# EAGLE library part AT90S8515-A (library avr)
MICROCONTROLLER 8 Kbytes FLASH 512 bytes SRAM 512 bytes EEPROM UART
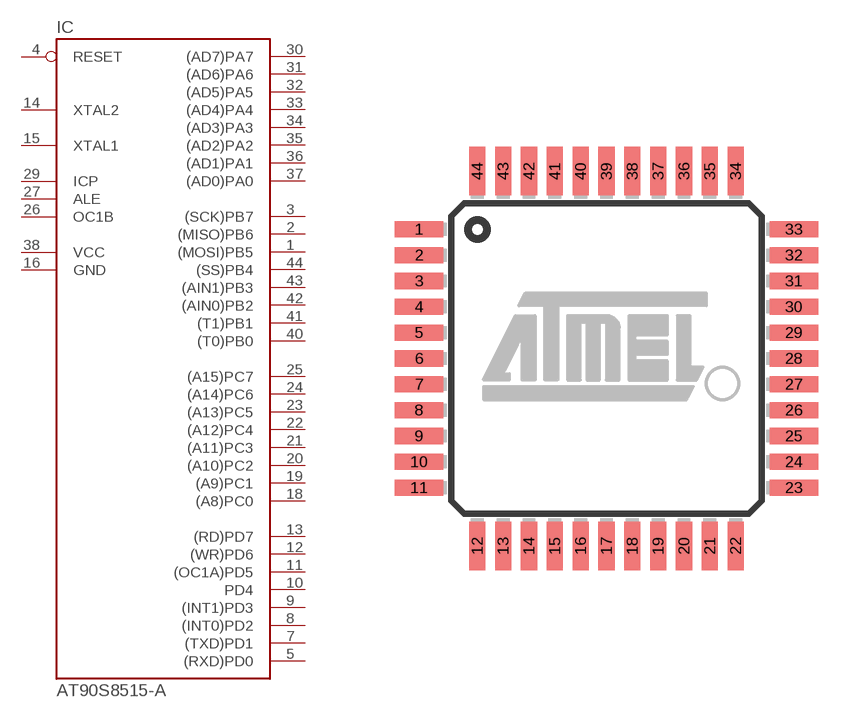
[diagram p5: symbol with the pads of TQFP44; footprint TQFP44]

Designator prefix IC

## AT90S8515-AA  [TQFP44]
1  (MOSI)PB5
2  (MISO)PB6
3  (SCK)PB7
4  RESET  in
5  (RXD)PD0
6  NC1  nc
7  (TXD)PD1
8  (INT0)PD2
9  (INT1)PD3
10  PD4
11  (OC1A)PD5
12  (WR)PD6
13  (RD)PD7
14  XTAL2
15  XTAL1
16  GND  pwr
17  NC2  nc
18  (A8)PC0
19  (A9)PC1
20  (A10)PC2
21  (A11)PC3
22  (A12)PC4
23  (A13)PC5
24  (A14)PC6
25  (A15)PC7
26  OC1B
27  ALE
28  NC3  nc
29  ICP
30  (AD7)PA7
31  (AD6)PA6
32  (AD5)PA5
33  (AD4)PA4
34  (AD3)PA3
35  (AD2)PA2
36  (AD1)PA1
37  (AD0)PA0
38  VCC  pwr
39  NC4  nc
40  (T0)PB0
41  (T1)PB1
42  (AIN0)PB2
43  (AIN1)PB3
44  (SS)PB4

## Footprint TQFP44 (pad centres in mm)
Thin Plasic Quad Flat Package
smd 1.5 x 0.5: 1 -5.8,4; 2 -5.8,3.2; 3 -5.8,2.4; 4 -5.8,1.6; 5 -5.8,0.8; 6 -5.8,0; 7 -5.8,-0.8; 8 -5.8,-1.6; 9 -5.8,-2.4; 10 -5.8,-3.2; 11 -5.8,-4; 23 5.8,-4; 24 5.8,-3.2; 25 5.8,-2.4; 26 5.8,-1.6; 27 5.8,-0.8; 28 5.8,0; 29 5.8,0.8; 30 5.8,1.6; 31 5.8,2.4; 32 5.8,3.2; 33 5.8,4
smd 0.5 x 1.5: 12 -4,-5.8; 13 -3.2,-5.8; 14 -2.4,-5.8; 15 -1.6,-5.8; 16 -0.8,-5.8; 17 0,-5.8; 18 0.8,-5.8; 19 1.6,-5.8; 20 2.4,-5.8; 21 3.2,-5.8; 22 4,-5.8; 34 4,5.8; 35 3.2,5.8; 36 2.4,5.8; 37 1.6,5.8; 38 0.8,5.8; 39 0,5.8; 40 -0.8,5.8; 41 -1.6,5.8; 42 -2.4,5.8; 43 -3.2,5.8; 44 -4,5.8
